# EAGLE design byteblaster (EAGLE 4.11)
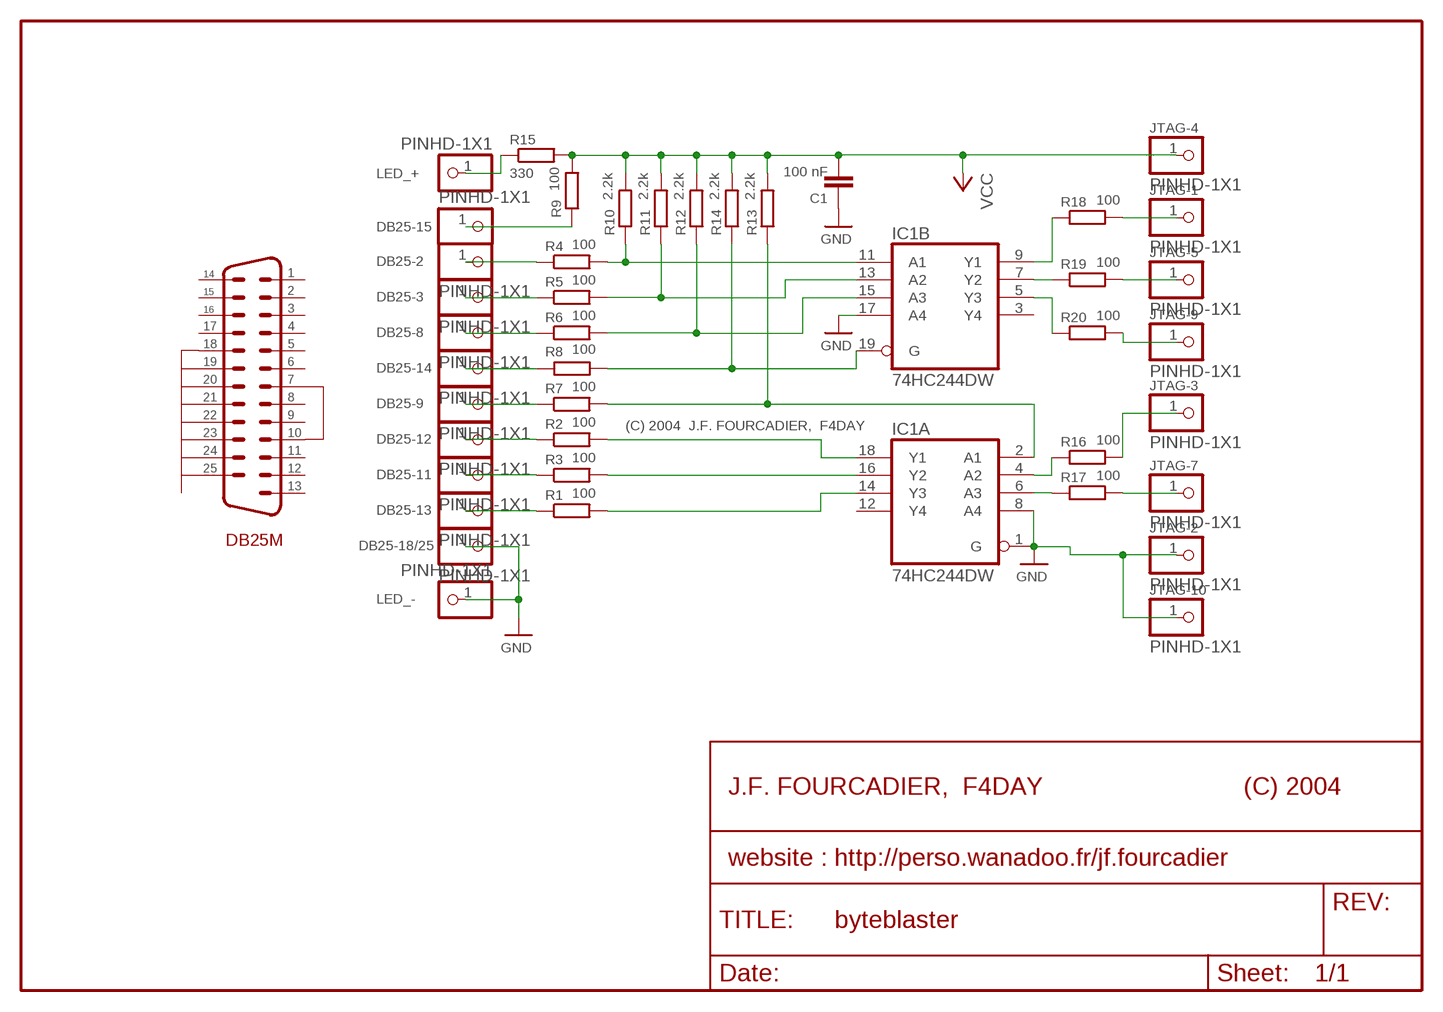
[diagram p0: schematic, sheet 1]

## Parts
C1  100 nF  C  [C1206]
DB25-2  PINHD-1X1  [1X01]
DB25-3  PINHD-1X1  [1X01]
DB25-8  PINHD-1X1  [1X01]
DB25-9  PINHD-1X1  [1X01]
DB25-11  PINHD-1X1  [1X01]
DB25-12  PINHD-1X1  [1X01]
DB25-13  PINHD-1X1  [1X01]
DB25-14  PINHD-1X1  [1X01]
DB25-15  PINHD-1X1  [1X01]
DB25-18/25  PINHD-1X1  [1X01]
IC1  74HC244DW  [SO20W]
JTAG-1  PINHD-1X1  [1X01]
JTAG-2  PINHD-1X1  [1X01]
JTAG-3  PINHD-1X1  [1X01]
JTAG-4  PINHD-1X1  [1X01]
JTAG-5  PINHD-1X1  [1X01]
JTAG-7  PINHD-1X1  [1X01]
JTAG-9  PINHD-1X1  [1X01]
JTAG-10  PINHD-1X1  [1X01]
LED_+  PINHD-1X1  [1X01]
LED_-  PINHD-1X1  [1X01]
R1  100  R-EU_R1206  [R1206]
R2  100  R-EU_R1206  [R1206]
R3  100  R-EU_R1206  [R1206]
R4  100  R-EU_R1206  [R1206]
R5  100  R-EU_R1206  [R1206]
R6  100  R-EU_R1206  [R1206]
R7  100  R-EU_R1206  [R1206]
R8  100  R-EU_R1206  [R1206]
R9  100  R-EU_R1206  [R1206]
R10  2.2k  R-EU_M1206  [M1206]
R11  2.2k  R-EU_M1206  [M1206]
R12  2.2k  R-EU_M1206  [M1206]
R13  2.2k  R-EU_M1206  [M1206]
R14  2.2k  R-EU_M1206  [M1206]
R15  330  R-EU_M1206  [M1206]
R16  100  R-EU_M1206  [M1206]
R17  100  R-EU_M1206  [M1206]
R18  100  R-EU_M1206  [M1206]
R19  100  R-EU_M1206  [M1206]
R20  100  R-EU_M1206  [M1206]

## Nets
GND: C1.1 DB25-18/25.1 IC1.1(A:G) IC1.8(A:A4) IC1.17(B:A4) JTAG-2.1 JTAG-10.1 LED_-.1
N$1: DB25-9.1 R7.1
N$2: DB25-3.1 R5.1
N$3: DB25-11.1 R3.1
N$4: LED_+.1 R15.1
N$5: DB25-2.1 R4.1
N$6: DB25-12.1 R2.1
N$7: DB25-8.1 R6.1
N$8: DB25-13.1 R1.1
N$9: DB25-14.1 R8.2
N$10: IC1.16(A:Y2) R3.2
N$11: JTAG-7.1 R17.2
N$12: IC1.14(A:Y3) R1.2
N$13: IC1.5(B:Y3) R20.1
N$14: IC1.11(B:A1) R4.2 R10.1
N$15: IC1.13(B:A2) R5.2 R11.1
N$16: IC1.15(B:A3) R6.2 R12.1
N$17: IC1.2(A:A1) R7.2 R13.1
N$18: IC1.18(A:Y1) R2.2
N$19: IC1.19(B:G) R8.1 R14.1
N$20: IC1.4(A:A2) R16.1
N$21: IC1.6(A:A3) R17.1
N$22: IC1.9(B:Y1) R18.1
N$23: IC1.7(B:Y2) R19.1
N$24: DB25-15.1 R9.1
N$25: JTAG-3.1 R16.2
N$26: JTAG-9.1 R20.2
N$27: JTAG-5.1 R19.2
N$28: JTAG-1.1 R18.2
VCC: C1.2 JTAG-4.1 R9.2 R10.2 R11.2 R12.2 R13.2 R14.2 R15.2
Unconnected: IC1.3(B:Y4) IC1.12(A:Y4)

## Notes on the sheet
- (C) 2004  J.F. FOURCADIER,  F4DAY
- DB25M

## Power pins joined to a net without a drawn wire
GND: IC1.10(P:GND)
VCC: IC1.20(P:VCC)

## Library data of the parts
C1 = capacitor-smd:C
DB25-2 DB25-3 DB25-8 DB25-9 DB25-11-DB25-15 DB25-18/25 JTAG-1-JTAG-5 JTAG-7 JTAG-9 JTAG-10 LED_+ LED_- = pinhead:PINHD-1X1: PIN HEADER
IC1 = 74xx-eu:74*244: Octal BUFFER and LINE DRIVER, 3-state
R1-R20 = rcl:R-EU_: RESISTOR, European symbol

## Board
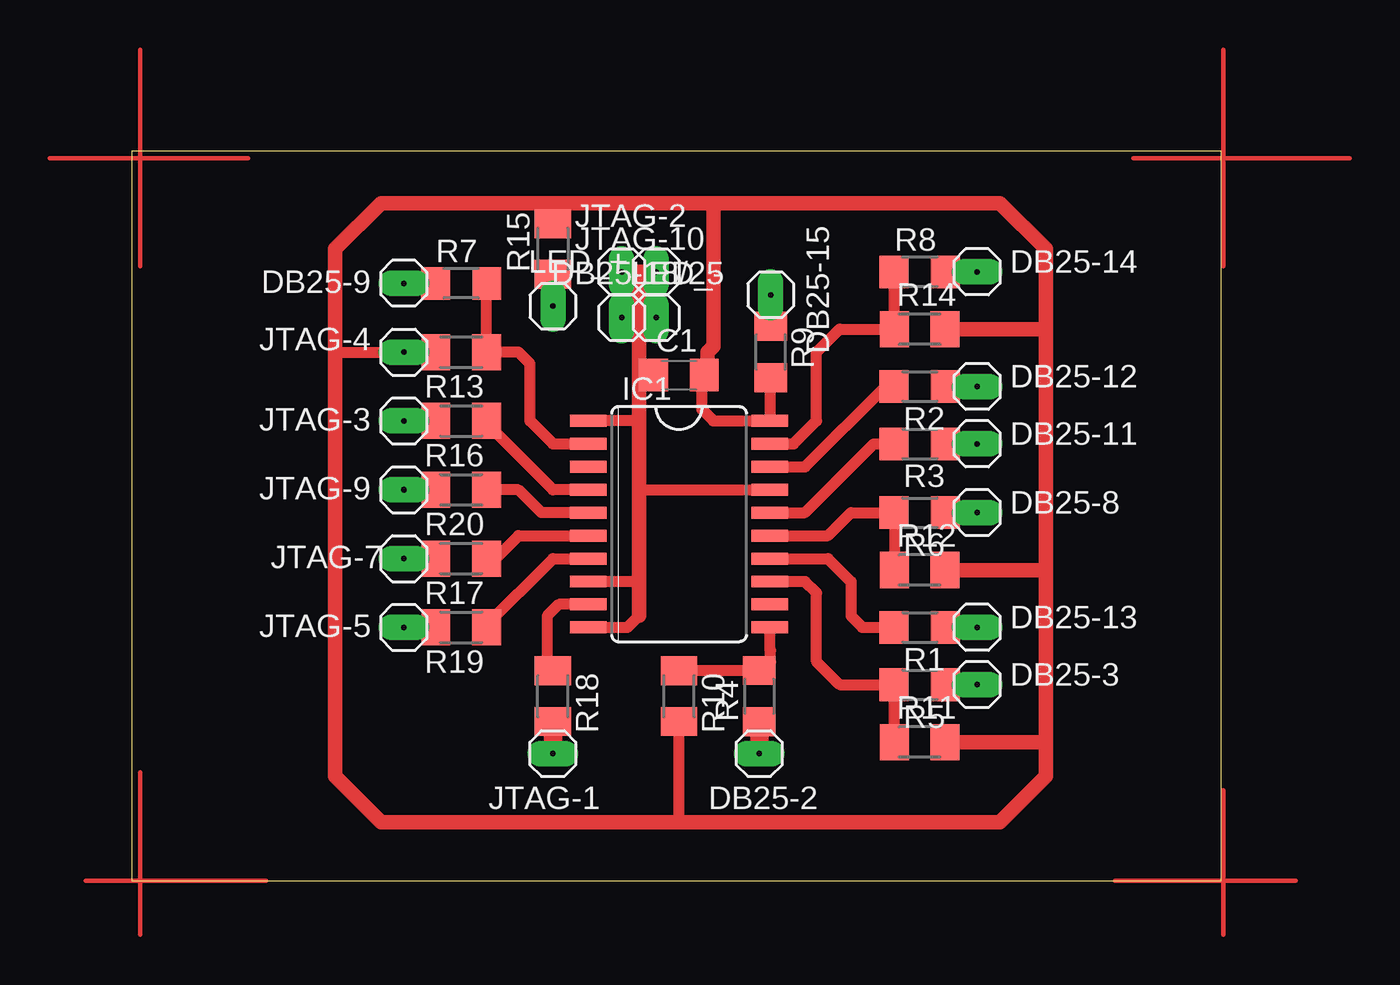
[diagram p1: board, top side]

Size 60.36 x 40.39 mm. Coordinates in mm from the lower left corner, seen from the top.
Outline: 0,0 60.36,0 60.36,40.39 0,40.39 0,0
Copper layers (1*16): Top 0.035mm / dielectric 1.5mm / GND 0.035mm
Design rules "default": minimum track width 10mil, minimum drill 24mil, track to track 8mil, track to pad 8mil, pad to pad 8mil, via to via 8mil, smd to smd 8mil, copper to edge 40mil, drill to drill 8mil, minimum pad ring 10mil, minimum via ring 8mil, stop-mask expansion 4mil, vias tented up to drill 0mil, thermal gap 10mil

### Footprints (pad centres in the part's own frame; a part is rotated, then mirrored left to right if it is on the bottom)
C1206 = smd 1.6 x 1.8: 1 -1.4,0; 2 1.4,0
1X01 = drill 0.305 pad 1.422 long: 1 0,0
SO20W = smd 0.66 x 2.032: 1 -5.715,-5.029; 2 -4.445,-5.029; 3 -3.175,-5.029; 4 -1.905,-5.029; 5 -0.635,-5.029; 6 0.635,-5.029; 7 1.905,-5.029; 8 3.175,-5.029; 9 4.445,-5.029; 10 5.715,-5.029; 11 5.715,5.029; 12 4.445,5.029; 13 3.175,5.029; 14 1.905,5.029; 15 0.635,5.029; 16 -0.635,5.029; 17 -1.905,5.029; 18 -3.175,5.029; 19 -4.445,5.029; 20 -5.715,5.029
R1206 = smd 1.6 x 1.803: 1 -1.422,0; 2 1.422,0
M1206 = smd 1.6 x 2: 1 -1.4,0; 2 1.4,0

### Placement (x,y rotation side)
C1  30.31,28 0 top
DB25-2  34.76,7.05 90 top
DB25-3  46.83,10.86 270 top
DB25-8  46.83,20.38 270 top
DB25-9  15.08,33.08 270 top
DB25-11  46.83,24.19 270 top
DB25-12  46.83,27.36 270 top
DB25-13  46.83,14.03 270 top
DB25-14  46.83,33.72 270 top
DB25-15  35.4,32.45 0 top
DB25-18/25  27.14,31.18 0 top
IC1  30.31,19.75 270 top
JTAG-1  23.33,7.05 90 top
JTAG-2  27.14,33.72 0 top
JTAG-3  15.08,25.46 90 top
JTAG-4  15.08,29.27 90 top
JTAG-5  15.08,14.03 90 top
JTAG-7  15.08,17.84 90 top
JTAG-9  15.08,21.65 90 top
JTAG-10  29.05,33.72 0 top
LED_+  23.33,31.81 0 top
LED_-  29.05,31.18 0 top
R1  43.65,14.03 180 top
R2  43.65,27.36 180 top
R3  43.65,24.19 180 top
R4  34.76,10.22 90 top
R5  43.65,10.86 180 top
R6  43.65,20.38 180 top
R7  18.25,33.08 0 top
R8  43.65,33.72 0 top
R9  35.4,29.27 270 top
R10  30.31,10.22 270 top
R11  43.65,7.68 0 top
R12  43.65,17.21 0 top
R13  18.25,29.27 180 top
R14  43.65,30.54 0 top
R15  23.33,34.98 90 top
R16  18.25,25.46 180 top
R17  18.25,17.84 180 top
R18  23.33,10.22 270 top
R19  18.25,14.03 180 top
R20  18.25,21.65 180 top

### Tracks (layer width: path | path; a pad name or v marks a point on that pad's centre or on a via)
GND
  Top 0.61: 25.23,14.03 IC1.10 27.46,14.03 28.09,14.67 | 24.92,16.57 IC1.8 28.09,16.57 | 28.09,25.46 IC1.1 | 28.09,21.65 IC1.17 | 28.09,28 C1.1
  Top 0.813: 28.09,33.72 JTAG-2.1 | 28.09,31.18 DB25-18/25.1 | 28.09,33.72 JTAG-10.1 | 28.09,31.18 28.09,33.72 | 28.09,31.18 LED_-.1 | 28.09,14.67 28.09,16.57 28.09,21.65 28.09,25.46 28.09,28 28.09,31.18
N$1
  Top 1.016: R7.1 DB25-9.1
N$2
  Top 1.016: R5.1 DB25-3.1
N$3
  Top 1.016: R3.1 DB25-11.1
N$4
  Top 0.813: R15.1 LED_+.1
N$5
  Top 1.016: R4.1 DB25-2.1
N$6
  Top 1.016: R2.1 DB25-12.1
N$7
  Top 1.016: R6.1 DB25-8.1
N$8
  Top 1.016: R1.1 DB25-13.1
N$9
  Top 1.016: R8.2 DB25-14.1
N$10
  Top 0.61: IC1.16 37.3,20.38 41.11,24.19 R3.2 42.38,24.19
N$11
  Top 1.016: R17.2 JTAG-7.1
N$12
  Top 0.61: IC1.14 38.57,17.84 39.84,16.57 39.84,14.67 40.48,14.03 R1.2
N$13
  Top 0.61: IC1.5 22.7,20.38 21.43,21.65 R20.1 19.52,21.65
N$14
  Top 0.61: IC1.11 35.34,12.81 35.4,12.76 35.4,12.12 34.76,11.49 R4.2 30.47,11.64 30.31,11.49 R10.1
N$15
  Top 0.61: IC1.13 37.3,16.57 37.94,15.93 37.94,12.12 39.2,10.86 R5.2 | R5.2 42.38,10.86 | R11.1 42.38,7.68 42.23,7.83 R5.2
N$16
  Top 0.61: IC1.15 38.57,19.11 39.84,20.38 R6.2 42.38,20.38 42.25,20.25 R12.1
N$17
  Top 0.61: IC1.2 23.33,24.19 22.06,25.46 22.06,28.64 21.43,29.27 R13.1 | R13.1 19.52,29.27 | R7.2 19.52,33.08 19.65,32.95 R13.1
N$18
  Top 0.61: IC1.18 37.3,22.92 41.75,27.36 R2.2
N$19
  Top 0.61: IC1.19 36.67,24.19 37.94,25.46 37.94,29.27 39.2,30.54 R14.1 42.25,33.59 42.38,33.72 R8.1
N$20
  Top 0.61: IC1.4 23.33,21.65 19.52,25.46 R16.1
N$21
  Top 0.61: 19.52,17.84 R17.1 20.16,17.84 21.43,19.11 IC1.6
N$22
  Top 0.61: IC1.9 23.65,15.3 23.01,14.67 23.01,11.49 23.14,11.62 R18.1
N$23
  Top 0.61: IC1.7 23.33,17.84 19.52,14.03 R19.1 20.16,14.03
N$24
  Top 0.813: DB25-15.1 R9.1
N$25
  Top 1.016: R16.2 JTAG-3.1
N$26
  Top 1.016: R20.2 JTAG-9.1
N$27
  Top 1.016: R19.2 JTAG-5.1
N$28
  Top 1.016: R18.2 JTAG-1.1
N$29
  Top 0.254: 0.47,6.01 0.47,-2.99
N$31
  Top 0.254: 54.47,0.01 64.47,0.01
N$33
  Top 0.254: 60.47,5.01 60.47,-2.99
N$34
  Top 0.254: 0.47,46.01 0.47,34.01
N$35
  Top 0.254: -2.53,0.01 7.47,0.01
N$36
  Top 0.254: 60.47,34.01 60.47,46.01
N$37
  Top 0.254: -4.53,40.01 6.47,40.01
N$38
  Top 0.254: 55.47,40.01 67.47,40.01
VCC
  Top 0.61: 11.27,29.27 JTAG-4.1 | 30.31,3.24 R10.2 | R9.2 35.4,25.46 IC1.20 32.22,25.46 31.59,26.1 31.59,28 C1.2
  Top 0.813: 23.33,37.53 13.81,37.53 11.27,34.98 11.27,29.27 11.27,5.78 13.81,3.24 30.31,3.24 48.09,3.24 50.64,5.78 50.64,7.68 | 23.33,37.53 32.22,37.53 | 50.64,7.68 50.64,17.21 | 50.64,17.21 50.64,30.54 | 50.64,30.54 50.64,34.98 48.09,37.53 32.22,37.53 | 50.64,30.54 R14.2 | 50.64,17.21 R12.2 | 44.92,7.68 R11.2 50.64,7.68 | 23.33,37.53 R15.2 | 32.22,37.53 32.22,29.59 31.9,29.27 31.9,28 C1.2
  Top 1.016: 16.98,29.27 R13.2 JTAG-4.1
